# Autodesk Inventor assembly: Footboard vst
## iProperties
Shininess: 20.0
Length Units: 11269
Angle Units: 11279
Time Units: 11290
Mass Units: 11283
Length Display Precision: 3
Angle Display Precision: 2
Created: 2001-04
Part Number: Footboard vst
Document SubType Name: Baugruppe
Designer: dl
Density: 0.0
Volumn: 0.0
Area: 0.0
PropertySet Name: Model Information
Control State: 0
Master: False
Checked Out: False
Author: dl
